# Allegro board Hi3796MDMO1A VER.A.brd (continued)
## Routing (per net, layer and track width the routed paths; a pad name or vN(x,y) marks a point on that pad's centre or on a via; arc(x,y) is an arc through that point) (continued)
VCC_SCI: length 20.9
  TOP w0.508: 108.97,18.8 111.12,20.95 112.39,20.95 114.05,22.61 v1(117.09,22.61)
  BOTTOM w0.508: R243.1 121.08,30.28 117.09,26.29 v1(117.09,22.61)
VDD_AUDIO: length 18.1
  TOP w0.356: U5.9 v1(73.46,90.75)
  TOP w0.381: R174.1 74.22,93.82 v1(73.96,94.08)
  TOP w0.508: R139.2 v1(62.71,92.61)
  BOTTOM w0.508: v1(62.71,92.61) 70.96,92.61 72.83,90.75 v1(73.46,90.75) 73.96,91.25 v1(73.96,94.08)
3136_ADDR0: length 2.4
  TOP w0.127: R3.1 83.64,70.15 84.27,69.52 U2.39
3136_ADDR1: length 2.7
  TOP w0.127: U2.38 84.51,69.92 83.26,71.17 R103.1
3136_DISEQC_IN: length 52.6
  TOP w0.127: v1(94.21,63.2) 94.16,63.25 92.46,63.25 91.95,63.75 91.95,64.26 91.69,64.52 91.69,65.28 91.05,65.92 U2.13
  TOP w0.508: v1(126.11,78.49) 126.24,78.61 Q6.3 126.24,80.67 124.97,81.94 R116.1 123.74,82.58 R51.1
  BOTTOM w0.127: v1(94.21,63.2) 94.69,62.71 104.75,62.71 110.16,68.12 120.4,68.12 126.11,73.84 v1(126.11,78.49)
3136_DISEQC_OUT: length 52.4
  TOP w0.127: U17.9 118.21,69.18 118.42,69.39 119.25,69.39 R123.1 119.77,69.1 120.05,68.82 120.05,58.02 118.7,56.67 110.92,56.67 108.36,54.1 103.28,54.1 102.23,55.14 102.23,55.88 101.42,56.69 101.42,58.5 v1(101.17,58.75) ; v1(91.82,63.12) 91.57,63.37 91.57,64.14 91.14,64.57 90.42,64.57 90.08,64.91 U2.12
  BOTTOM w0.127: v1(91.82,63.12) 91.82,63.02 95.15,59.69 99.03,59.69 99.64,59.08 100.84,59.08 v1(101.17,58.75)
3136_FUNC_SEL: length 3.1
  TOP w0.127: U2.14 91.16,66.32 91.95,65.53 91.95,64.8 R4.1
3136_HV_SEL: length 46
  TOP w0.127: v1(101.22,60.17) 101.75,59.64 101.75,56.72 102.49,55.98 102.49,55.25 103.38,54.36 108.13,54.36 110.74,56.97 118.26,56.97 119.67,58.38 119.67,60.06 118.21,61.52 U17.8 ; v1(92.58,67.97) 92.54,67.92 U2.18
  BOTTOM w0.127: v1(101.22,60.17) 100.97,59.92 99.95,59.92 99.54,60.33 97.45,60.33 96.67,61.1 94.57,61.1 93.81,61.86 93.07,62.61 93.07,67.49 92.63,67.92 92.63,67.92 v1(92.58,67.97)
3136_I2C_SCL: length 19
  TOP w0.127: U2.41 84.54,68.72 84.45,68.81 83.95,68.81 83.5,68.36 83.32,68.36 C221.1 82.83,68.17 82.55,68.45 80.92,68.45 R108.2 80.42,68.05 80,68.47 77.13,68.47 74.3,65.63 74.3,64.34 72.82,62.87 72.72,62.87 72.39,62.53 72.39,62.15 72.14,61.9 71.54,61.9 U10.D26
3136_I2C_SDA: length 17.8
  TOP w0.127: U2.40 84.58,69.12 84.52,69.06 83.82,69.06 83.44,68.68 83.36,68.68 C217.1 82.83,68.99 82.55,68.71 80.95,68.71 R104.2 80.42,69.14 80,68.72 76.9,68.72 73.91,65.74 73.91,64.42 72.21,62.71 72.01,62.51 72.01,62.37 U10.C27
3136_IOUT_N: length 30.5
  TOP w0.114: U2.32 87.28,71.58 87.35,71.65 87.35,76.17 90.3,79.12 95,79.12 98.1,82.22 98.1,89.52 99.93,91.35 101.33,91.35 C307.2
3136_IOUT_P: length 30.5
  TOP w0.114: U2.31 87.68,71.58 87.62,71.65 87.62,72.1 87.73,72.21 87.73,72.53 87.62,72.64 87.62,76.06 90.41,78.85 95.11,78.85 98.36,82.11 98.36,89.41 98.7,89.75 98.97,89.75 99.16,89.94 99.16,90.2 99.35,90.39 99.61,90.39 99.81,90.59 99.81,90.85 100.04,91.08 101.26,91.08 C303.2
3136_LNB_EN: length 45.3
  TOP w0.127: U17.5 116.26,61.06 117.51,59.8 117.51,57.76 116.98,57.23 110.57,57.23 107.95,54.61 103.49,54.61 102.75,55.35 102.75,56.09 102.03,56.8 102.03,60.15 101.45,60.73 100.66,60.73 v1(100.33,60.4) ; v1(91.49,68.81) 91.49,68.94 91.31,69.12 U2.21
  BOTTOM w0.127: v1(91.49,68.81) 91.77,69.09 92.38,69.09 93.45,68.02 93.45,62.71 94.67,61.49 96.85,61.49 97.66,60.68 100.05,60.68 v1(100.33,60.4)
3136_QOUT_N: length 33.7
  TOP w0.114: C186.2 101.26,93.88 100.4,93.88 96.84,90.32 96.84,82.74 94.49,80.39 89.66,80.39 85.98,76.71 85.98,74.23 86.13,74.08 86.13,73.78 85.98,73.62 85.98,73.32 86.13,73.17 86.13,72.86 85.98,72.71 85.98,71.5 86.08,71.4 U2.35
3136_QOUT_P: length 33.7
  TOP w0.114: U2.36 85.68,71.45 85.71,71.48 85.71,76.82 89.55,80.66 94.38,80.66 96.57,82.85 96.57,90.43 100.29,94.15 101.23,94.15 C306.2
3136_RF_AGC: length 35.6
  TOP w0.127: R60.1 100.19,95.83 95.32,90.96 95.32,83.25 93.85,81.79 88.95,81.79 84.58,77.42 84.58,75.56 83.95,74.93 82.3,74.93 82.02,74.65 C37.1 R127.2
3136_RSTN: length 34.7
  TOP w0.127: U10.C28 74.68,64.24 74.68,65.33 v1(77.22,67.87) ; U2.15 91.14,66.72 91.64,66.22 C38.1 R83.1 92.56,64.85 92.71,64.69 94.61,64.69 94.87,64.44 94.87,62.99 94.41,62.53 86.87,62.53 86.28,63.12 83.57,63.12 v1(83.31,63.37)
  BOTTOM w0.127: v1(77.22,67.87) 78.66,66.42 78.99,66.42 82.04,63.37 v1(83.31,63.37)
3136_TS_CLK: length 3.2
  TOP w0.127: R10.2 83.11,64.82 84.3,66.01 84.3,66.37 84.66,66.72 U2.46
3136_TS_OUT0: length 6.2
  TOP w0.127: U2.48 84.8,65.92 84.58,65.7 84.58,64.64 83.82,63.88 82.93,63.88 82.55,63.5 R13.2
3136_TS_SYNC: length 2.6
  TOP w0.127: R226.2 83.79,67.82 84.35,67.82 84.46,67.92 U2.43
3136_TS_VAL: length 6.5
  TOP w0.127: U2.44 84.06,67.52 83.69,67.16 83.69,66.17 83.36,65.84 R5.2 82.83,66.22 82.7,66.34 80.92,66.34 C176.1
3136_XIN: length 12.9
  TOP w0.203: U2.23 91.6,69.92 92.01,69.51 92.47,69.51 92.81,69.16 R24.1 93.42,69.24 C172.1
  TOP w0.254: C172.1 98.02,69.24 98.68,69.9 X1.2
3136_XOUT: length 12.5
  TOP w0.203: C174.1 93.55,68.15 R24.2 93.07,68.63 92.84,68.63 92.29,69.18 91.86,69.18 91.51,69.52 U2.22
  TOP w0.254: C174.1 95.28,68.15 95.76,68.63 98.3,68.63 98.68,68.25 X1.1
AC2012_SCL_T: length 25.2
  TOP w0.127: U2.27 89.28,71.37 89.75,71.84 89.75,72.46 89.48,72.73 89.47,72.73 R65.2 89.13,73.53 89.26,73.53 89.42,73.7 89.42,75.43 91.72,77.72 95.5,77.72 99.51,81.73 99.51,85.73 101.18,87.4 101.33,87.4 R61.2
AC2012_SDA_T: length 24.5
  TOP w0.127: U2.26 89.68,71.41 90,71.74 90,72.71 90.2,72.9 R66.2 90.02,73.3 89.67,73.65 89.67,75.32 91.82,77.47 95.61,77.47 99.76,81.62 99.76,85.62 101.29,87.15 101.41,87.15 R62.2
ADAC_VOUTL: length 21.8
  TOP w0.203: U10.D23 69.19,61.95 69.19,62.53
  TOP w0.254: 69.19,62.53 69.19,62.81 69.14,62.87 69.14,63.42 70.1,64.39 70.1,66.08 70.48,66.46 70.48,66.47 70.48,79.5 69.52,80.47 R138.1 69.52,81.48 69.46,81.55 C350.2
ADAC_VOUTR: length 20.7
  TOP w0.254: C351.1 68.31,81.6 68.15,81.43 R183.1 68.15,80.06 69.47,78.74 69.47,67.06 68.94,66.52 68.94,63.91 68.76,63.73 68.76,62.35 U10.C23
ADAC_VREF: length 1.9
  TOP w0.254: U10.G18 v2(65.18,59.54)
  BOTTOM w0.381: C250.2 65.96,58.75 v2(65.18,59.54)
AUDIO_L: length 11.3
  TOP w0.254: J34.3 65.53,103.87 65.53,100.2 66.42,99.31 67.99,99.31 68.63,98.67 C339.1 68.61,97.71 68.61,96.69 R119.2
AUDIO_R: length 14
  TOP w0.254: J34.2 66.8,107.7 64.8,105.69 64.8,99.97 66.19,98.58 67.16,98.58 67.54,98.2 C140.1 R74.1
CORE_CTRL: length 4
  TOP w0.127: U10.E27 72.51,61.27 72.83,61.27 73.78,62.22 v1(73.78,62.53)
  BOTTOM w0.127: v1(73.78,62.53) 73.78,63.06 R23.2
CPU_CTRL: length 7.1
  TOP w0.127: U10.E28 72.85,60.74 74.26,62.14 74.26,63.11 75.54,64.39 v1(75.92,64.39)
  BOTTOM w0.127: R21.2 76.58,63.88 76.07,64.39 v1(75.92,64.39)
CVBS: length 37.3
  TOP w0.254: U10.A25 70.61,64.17 70.61,65.02 71.75,66.17 71.75,80.9 72.14,81.28 72.14,85.09 74.47,87.43 76.22,87.43 78.26,89.46 R9.1 C79.1 78.26,95.92 L6.1 78.26,95.95 C80.1
CVBS_OUT: length 15.2
  TOP w0.305: L6.2 77.46,96.94 C80.2 C17.1 76.31,97.97 76,97.66 D9.3 74.93,98.93 72.26,101.6 69.55,101.6 69.09,101.14 J34.4
DDR_ADDR0: length 76.2
  TOP w0.127: U10.AF13 61.17,43.54 61.17,39.21 55.62,33.66 54.39,32.43 42.78,32.43 41.74,31.39 34.13,31.39 32.34,33.18 32.34,33.92 30.93,35.32 v2(30.93,40.4) 31.23,40.4 31.56,40.73 31.56,41.23 31.74,41.42 34.39,41.42 34.8,41.82 34.8,42.32 35.39,42.91 U6.N3 ; U3.N3 35.39,59.28 34.75,58.64 34.75,58.27 34.33,57.85 31.62,57.85 31.39,57.63 31.39,57.27 v2(30.93,56.81)
  BOTTOM w0.127: v2(30.93,56.81) 30.68,56.56 30.68,51.7 31.57,50.81 31.57,49.03 30.05,47.5 30.05,43.88 31.56,42.37 31.56,40.98 30.98,40.4 v2(30.93,40.4)
DDR_ADDR1: length 53.3
  TOP w0.127: U6.P7 v2(34.99,39.43) ; U3.P7 v2(34.99,55.84) ; U10.AE12 v2(59.58,44.34)
  BOTTOM w0.127: v2(59.58,44.34) 59.18,43.94 59.18,41.4 52.87,35.1 36.85,35.1 36.01,35.93 36.01,37.22 35.79,37.45 35.79,37.9 35.38,38.3 35.38,38.79 34.99,39.18 v2(34.99,39.43) 34.99,40.69 35.89,41.59 35.89,43.07 34.2,44.76 34.2,45.4 34.62,45.83 34.62,47.57 35,47.96 35,51.8 34.74,52.06 34.74,54.32 35.07,54.64 35.2,54.64 35.38,54.83 35.38,55.44 v2(34.99,55.84)
DDR_ADDR2: length 78.5
  TOP w0.127: U3.P3 34.59,59.33 33.39,58.13 31.42,58.13 v2(30.93,57.65) ; v2(30.93,41.24) 30.93,41.38 31.43,41.87 33.59,41.87 34.59,42.87 U6.P3 ; U10.AD15 v2(62.78,45.14)
  BOTTOM w0.127: v2(62.78,45.14) 63.17,44.74 63.17,43.03 62.76,42.62 62.76,41.08 52.65,30.96 46.35,30.96 44.71,29.32 37.03,29.32 33.83,32.52 33.83,33.59 30.07,37.35 30.07,40.79 30.52,41.24 v2(30.93,41.24) 30.68,41.49 30.68,42.15 29.29,43.54 29.29,47.94 31.19,49.84 31.19,50.68 30.3,51.57 30.3,57.02 v2(30.93,57.65)
DDR_ADDR3: length 65.3
  TOP w0.127: U3.N2 35.76,59.86 35.76,59.04 v2(35.23,58.51) ; v2(35.23,42.1) 35.76,42.63 35.76,43.46 U6.N2 ; v2(43,31.99) 54.67,31.99 62.38,39.69 U10.AH15
  BOTTOM w0.127: v2(35.23,58.51) 35.23,56.64 33.78,55.19 33.78,54.75 34.26,54.27 34.26,51.6 34.24,51.58 34.24,48.37 32.84,46.97 32.84,45.47 32.99,45.32 32.99,44.83 35.23,42.6 v2(35.23,42.1) 34.19,41.06 34.19,35.8 38,31.99 v2(43,31.99)
DDR_ADDR4: length 55.9
  TOP w0.127: U3.P8 v2(34.99,55.04) ; U6.P8 v2(34.99,38.63) ; U10.AD13 v2(60.38,45.14)
  BOTTOM w0.127: v2(34.99,55.04) 34.69,54.74 34.49,54.54 34.49,51.83 34.62,51.7 34.62,48.34 33.24,46.96 33.24,45.15 35.63,42.76 35.63,41.82 34.6,40.78 34.6,39.02 v2(34.99,38.63) 34.99,37.4 34.99,37.39 34.99,35.58 36.43,34.14 52.46,34.14 59.56,41.25 59.56,42.95 59.97,43.36 59.97,44.73 v2(60.38,45.14)
DDR_ADDR5: length 81.2
  TOP w0.127: U10.AE16 v2(63.58,44.34) ; U3.P2 34.97,59.85 34.97,59.27 34.24,58.54 v2(34.24,58.4) ; v2(31.84,33.71) 30.51,35.04 30.51,40.62 30.74,40.84 31.1,40.84 31.33,41.07 31.33,41.38 31.59,41.64 33.93,41.64 v2(34.34,42.05) 34.34,42.24 34.97,42.88 34.97,43.44 U6.P2
  BOTTOM w0.127: v2(34.24,58.4) 34.24,56.1 33.38,55.24 33.38,51.89 33.86,51.42 33.86,48.39 32.18,46.72 32.18,44.79 34.34,42.64 v2(34.34,42.05) ; v2(63.58,44.34) 64.77,43.14 64.77,40.85 51.72,27.79 36.4,27.79 31.92,32.27 31.92,33.63 v2(31.84,33.71)
DDR_ADDR6: length 57.8
  TOP w0.127: U10.AF11 58.8,43.56 58.8,42.98 59.18,42.6 59.18,38.97 53.82,33.61 41.87,33.61 41.16,32.91 36.47,32.91 33.39,35.99 v2(33.39,38.63) U6.R8 ; v2(32.59,55.04) 33.39,55.04 U3.R8
  BOTTOM w0.127: v2(33.39,38.63) 33.39,38.78 33,39.18 33,42.96 31.52,44.44 31.52,47.02 33.1,48.6 33.1,51.21 32.21,52.1 32.21,54.46 32.59,54.84 v2(32.59,55.04)
DDR_ADDR7: length 76.2
  TOP w0.127: U10.AG15 62.81,42.71 62.81,39.49 54.11,30.8 34.11,30.8 30.13,34.78 30.13,41.08 31.15,42.1 33.38,42.1 34.19,42.9 34.19,43.43 U6.R2 33.79,44.09 33.37,44.5 33.37,44.92 32.59,45.7 31.95,45.7 29.11,48.55 29.11,56.46 31.09,58.44 33.34,58.44 34.16,59.27 34.16,59.86 U3.R2
DDR_ADDR8: length 58.7
  TOP w0.127: U10.AG12 59.56,42.72 59.56,38.79 54.01,33.23 42.21,33.23 41.31,32.33 36.44,32.33 32.59,36.18 32.59,38.21 32.59,38.21 v2(32.59,38.63) U6.T8 ; U3.T8 32.11,55.44 v2(31.76,55.09)
  BOTTOM w0.127: v2(31.76,55.09) 31.45,54.77 31.45,51.9 32.34,51.01 32.34,48.8 30.81,47.28 30.81,44.13 32.38,42.56 32.38,40.73 32.08,40.43 32.08,39.13 v2(32.59,38.63)
DDR_ADDR9: length 82.6
  TOP w0.127: U3.R3 33.79,59.32 33.24,58.77 30.85,58.77 28.73,56.64 28.73,48.17 32.66,44.24 33.12,44.24 33.4,43.95 33.4,43.65 33.79,43.26 U6.R3 33.79,42.91 33.21,42.33 30.87,42.33 29.75,41.21 29.75,34.5 v2(31.39,32.86) ; U10.AE17 v2(64.38,44.34)
  BOTTOM w0.127: v2(64.38,44.34) 65.15,43.56 65.15,40.64 51.92,27.41 36.23,27.41 31.39,32.25 v2(31.39,32.86)
DDR_ADDR10: length 48.3
  TOP w0.127: U3.L7 v2(36.59,56.64) ; U10.AE9 v2(57.18,44.34) ; U6.L7 v2(36.59,40.23)
  BOTTOM w0.127: v2(36.59,56.64) 36.98,56.24 36.98,55.67 36.9,55.59 36.9,44.87 37.01,44.77 37.01,40.64 v2(36.59,40.23) 37,39.82 37,39.19 36.93,39.12 36.93,38.47 37.13,38.27 37.13,36.69 37.67,36.15 38.28,36.15 38.37,36.24 52.26,36.24 57.53,41.51 57.53,42.98 57.66,43.1 57.66,43.86 v2(57.18,44.34)
DDR_ADDR11: length 56
  TOP w0.127: U10.AG10 58.38,42.89 58.8,42.47 58.8,39.13 53.66,33.99 41.56,33.99 40.86,33.29 36.69,33.29 34.19,35.8 34.19,39.43 U6.R7 v2(33.39,39.43) ; U3.R7 v2(33.39,55.84)
  BOTTOM w0.127: v2(33.39,39.43) 33.39,43.08 31.85,44.61 31.85,46.87 33.48,48.5 33.48,51.31 32.59,52.2 32.59,54.34 33.09,54.84 33.09,55.54 v2(33.39,55.84)
DDR_ADDR12: length 50.8
  TOP w0.127: U10.AE11 v2(58.78,44.34) ; U3.N7 v2(35.79,55.84) ; U6.N7 v2(35.79,39.43)
  BOTTOM w0.127: v2(58.78,44.34) 58.78,41.54 52.72,35.48 37.1,35.48 36.6,35.98 36.6,37.84 36.18,38.25 36.18,39.03 v2(35.79,39.43) 35.79,40.53 36.42,41.16 36.42,43.85 35.79,44.49 35.79,45.4 36.22,45.84 36.22,53.43 35.79,53.86 35.79,54.24 36.22,54.67 36.22,55.18 35.79,55.61 v2(35.79,55.84)
DDR_ADDR13: length 81.2
  TOP w0.127: U3.T3 32.69,59.44 32.64,59.49 30.46,59.49 27.97,57 27.97,47.66 32.21,43.42 32.6,43.42 U6.T3 32.91,42.94 31.59,42.94 31.25,43.29 29.47,43.29 28.98,42.8 28.98,33.97 33.41,29.54 53.49,29.54 63.37,39.42 63.37,40.89 64.64,42.16 64.64,43.27 U10.AF17
DDR_ADDR14: length 59.5
  TOP w0.127: U3.T7 v2(32.59,55.84) ; U10.AF12 v2(60.38,43.54) ; U6.T7 v2(32.59,39.43)
  BOTTOM w0.127: v2(32.59,55.84) 32.15,55.4 32.15,54.92 31.83,54.6 31.83,52 32.72,51.11 32.72,48.7 31.19,47.17 31.19,44.26 32.61,42.84 32.61,39.87 32.59,39.85 v2(32.59,39.43) 32.59,39.18 32.98,38.79 32.98,38.35 32.34,37.7 32.34,36.81 32.77,36.37 33.03,36.37 37.92,31.48 43.37,31.48 45.32,33.42 52.28,33.42 59.94,41.09 59.94,42.88 60.38,43.31 v2(60.38,43.54)
DDR_ADDR15: length 50.6
  TOP w0.127: U10.AD11 v2(58.78,45.14) ; U6.M7 v2(36.59,39.43) ; U3.M7 v2(35.79,56.64)
  BOTTOM w0.127: v2(35.79,56.64) 35.79,56.45 36.19,56.05 36.19,55.64 36.58,55.25 36.58,44.61 36.73,44.46 36.73,41.01 36.12,40.4 36.12,39.9 v2(36.59,39.43) 36.59,38.33 36.85,38.06 36.85,36.36 37.35,35.86 52.47,35.86 57.91,41.3 57.91,42.65 58.37,43.1 58.37,44.73 v2(58.78,45.14)
DDR_BA0: length 80.5
  TOP w0.127: U10.AH16 v2(63.58,41.94) ; v2(32.88,33.34) 32.88,34.01 31.32,35.57 31.32,39.77 32.43,40.88 35.14,40.88 36.58,42.32 36.58,43.29 36.19,43.68 U6.M2 36.07,43.94 35.85,43.94 35.58,44.21 35.28,44.21 35,44.49 35,45.01 35,45.01 35,45.43 34.73,45.7 33.22,45.7 32.72,46.21 32.08,46.21 29.49,48.8 29.49,54.35 32.36,57.22 34.95,57.22 36.6,58.87 36.6,59.82 U3.M2
  BOTTOM w0.127: v2(63.58,41.94) 63.58,40.77 52.93,30.12 46.71,30.12 45.14,28.56 36.71,28.56 32.88,32.39 v2(32.88,33.34)
DDR_BA1: length 53.2
  TOP w0.127: U6.N8 v2(35.79,38.63) 35.79,37.43 35.96,37.25 35.96,35.33 35.81,35.18 35.81,34.76 36.82,33.75 40.61,33.75 41.23,34.38 53.5,34.38 57.98,38.85 57.98,43.54 U10.AF10 ; U3.N8 v2(35.79,55.04)
  BOTTOM w0.127: v2(35.79,55.04) 35.79,54.78 35.42,54.4 35.23,54.4 35,54.17 35,52.27 35.38,51.88 35.38,47.78 35,47.39 35,44.67 36.14,43.52 36.14,41.36 35.4,40.62 35.4,39.19 35.79,38.8 v2(35.79,38.63)
DDR_BA2: length 73
  TOP w0.127: U3.M3 36.19,58.89 34.83,57.52 32.06,57.52 v2(31.95,57.42) ; U6.M3 36.19,42.44 34.91,41.16 32.1,41.16 v2(31.95,41.01) ; U10.AE13 v2(60.38,44.34)
  BOTTOM w0.127: v2(60.38,44.34) 60.38,44.09 60.83,43.64 60.83,42.6 60.33,42.09 60.33,40.93 52.34,32.94 45.47,32.94 43.62,31.1 37.54,31.1 31.57,37.07 31.57,40.63 v2(31.95,41.01) 31.95,42.48 30.43,44 30.43,47.38 31.95,48.9 31.95,50.91 31.07,51.8 31.07,55.73 31.95,56.62 v2(31.95,57.42)
DDR_CASN: length 83.9
  TOP w0.127: U3.K3 v2(38.19,59.04) ; U10.AE15 v2(62.78,44.34) ; U6.K3 37.79,43.29 37.39,43.69 37.39,45.02 v2(37.69,45.32) 37.69,45.57 34.09,49.16 v2(31.11,49.16)
  BOTTOM w0.127: v2(38.19,59.04) 37.89,58.74 37.89,57.57 37.93,57.54 37.93,57.53 38.16,57.3 38.16,57.3 38.48,56.99 38.48,53.76 38.2,53.48 38.2,47.28 38.38,47.1 38.38,46.02 v2(37.69,45.32) ; v2(62.78,44.34) 62.37,43.93 62.37,41.22 52.62,31.47 46.1,31.47 44.33,29.7 37.19,29.7 34.23,32.65 34.23,33.85 30.52,37.56 30.52,40.65 30.71,40.84 31.1,40.84 31.33,41.07 31.33,41.4 31.07,41.66 31.07,42.27 29.67,43.67 29.67,47.72 v2(31.11,49.16)
DDR_CKE: length 45
  TOP w0.127: U3.K9 v2(37.39,54.24) ; v2(38.28,37.1) 37.79,37.59 U6.K9 ; U10.AD10 v2(57.98,45.14)
  BOTTOM w0.127: v2(37.39,54.24) 37.18,54.03 37.18,45.15 37.49,44.84 37.49,41.97 37.88,41.58 37.88,39.72 37.88,39.72 37.88,39.13 38.28,38.74 v2(38.28,37.1) 52.52,37.1 56.77,41.35 R130.2 56.77,42.97 56.77,42.98 56.77,44.53 56.99,44.74 57.58,44.74 v2(57.98,45.14)
DDR_CLK1N: length 45.4
  TOP w0.114: R37.1 55.36,37.94 52.21,34.79 41.36,34.79 39.38,36.77 39.25,36.77 38.47,37.55 38.47,37.83 38.23,38.07 38.23,39.17 37.79,39.6 U6.K7 ; U3.K7 38.06,56.5 38.06,56.82 38.59,57.35 38.59,57.48 v2(38.37,57.7)
  TOP w0.127: U6.K7 37.79,40.33 38.31,40.86 v2(38.61,40.86)
  BOTTOM w0.114: R11.2 38.72,58.08 38.72,57.95 38.47,57.7 v2(38.37,57.7) 38.73,57.34 38.73,40.99 v2(38.61,40.86) 38.82,40.65 38.82,39.83 R15.2
DDR_CLK1P: length 44.8
  TOP w0.114: v2(39.08,57.7) 38.86,57.48 38.86,57.24 38.32,56.71 38.32,56.5 U3.J7 ; U6.J7 38.99,39.43 38.99,38.14 38.73,37.89 38.73,37.66 39.36,37.03 39.49,37.03 40.08,36.44 40.25,36.44 40.3,36.44 40.51,36.22 40.51,36.06 40.51,36.01 40.73,35.79 40.89,35.79 40.97,35.79 41.16,35.6 41.16,35.41 41.16,35.36 41.47,35.05 52.1,35.05 55.24,38.19 R36.1
  TOP w0.127: v2(39.32,40.86) 39.18,40.86 38.81,40.49 38.81,40.05 U6.J7
  BOTTOM w0.114: R15.1 39.08,39.81 39.08,40.63 v2(39.32,40.86) 39.14,40.86 39,41 39,57.62 v2(39.08,57.7) 38.99,57.79 38.99,58.06 R11.1
DDR_CSN: length 73.5
  TOP w0.127: U10.AH13 60.78,39.36 54.26,32.85 42.52,32.85 41.55,31.88 36.31,31.88 32.08,36.1 32.08,39.64 32.82,40.38 35.65,40.38 37.41,42.14 37.41,43.26 36.99,43.68 U6.L2 36.99,44.01 36.59,44.41 36.59,45.49 35.62,46.46 33.73,46.46 32.97,47.23 32.34,47.23 30.25,49.31 30.25,54.18 32.7,56.63 35.2,56.63 37.39,58.81 37.39,59.84 U3.L2
DDR_DM0: length 16.8
  TOP w0.127: v2(42.19,55.84) U3.E7 ; U10.R4 v2(53.18,52.34)
  BOTTOM w0.127: v2(53.18,52.34) 52.58,51.74 50.04,51.74 48.26,53.52 48.26,55.55 46.16,57.65 44.01,57.65 v2(42.19,55.84)
DDR_DM1: length 16.7
  TOP w0.127: U10.T5 54.38,51.94 v2(53.98,52.34) ; U3.D3 v2(42.99,59.84)
  BOTTOM w0.127: v2(53.98,52.34) 53.57,52.74 51.68,52.74 51.18,52.25 50.27,52.25 48.64,53.88 48.64,55.76 45.17,59.23 43.6,59.23 v2(42.99,59.84)
DDR_DM2: length 11.1
  TOP w0.127: U6.E7 v2(42.19,40.23) ; U10.AF1 v2(50.78,43.54)
  BOTTOM w0.127: v2(50.78,43.54) 47.47,40.23 v2(42.19,40.23)
DDR_DM3: length 11.3
  TOP w0.127: U10.AE2 v2(51.58,44.34) ; U6.D3 v2(42.99,42.63)
  BOTTOM w0.127: v2(42.99,42.63) 43.6,42.02 47.68,42.02 50.44,44.78 51.13,44.78 v2(51.58,44.34)
DDR_DQ0: length 18.9
  TOP w0.127: U10.N4 v2(53.18,54.74) ; U3.E3 v2(41.39,59.84)
  BOTTOM w0.127: v2(41.39,59.84) 41.39,60.57 41.91,61.09 41.91,61.85 42.22,62.16 44.72,62.16 47.1,59.77 47.1,59.45 49.91,56.64 49.91,55.75 51.33,54.33 52.77,54.33 v2(53.18,54.74)
DDR_DQ1: length 13.5
  TOP w0.127: U3.F7 41.38,55.84 41.38,54.43 42.24,53.58 45.48,53.58 48.59,50.47 51.04,50.47 U10.V1
DDR_DQ2: length 16.5
  TOP w0.127: U3.F2 41.39,60.64 41.39,61.93 41.93,62.47 44.83,62.47 46.23,61.07 46.23,59.69 47.5,58.42 49.16,56.76 49.16,55.91 50.73,54.34 U10.N1
DDR_DQ3: length 15.8
  TOP w0.127: U10.W3 52.35,49.96 50.98,49.96 50.88,50.06 50.32,50.06 50.22,49.96 47.8,49.96 44.7,53.07 41.46,53.07 40.6,53.93 40.6,55.04 U3.F8
DDR_DQ4: length 21.2
  TOP w0.127: v2(40.59,59.84) 39.79,59.84 U3.H3 ; U10.N5 v2(53.98,54.74)
  BOTTOM w0.127: v2(53.98,54.74) 53.57,55.14 51.28,55.14 50.35,56.08 50.35,57.45 47.75,60.05 47.47,60.05 44.95,62.57 42.04,62.57 41.61,62.13 41.61,61.34 40.59,60.33 v2(40.59,59.84)
DDR_DQ5: length 17.8
  TOP w0.127: U3.H8 39,55.04 39,53.93 41.34,51.59 44.17,51.59 46.89,48.87 51.49,48.87 51.71,49.1 52.41,49.1 U10.Y3
DDR_DQ6: length 18.5
  TOP w0.127: U3.G2 40.59,60.63 40.59,61.95 41.48,62.85 44.99,62.85 46.74,61.1 46.74,59.72 49.54,56.92 49.54,56.07 50.82,54.79 51.52,54.79 U10.N2
DDR_DQ7: length 16.8
  TOP w0.127: U10.W2 51.67,49.54 51.28,49.15 50.29,49.15 50.06,49.38 47.63,49.38 44.45,52.56 41.17,52.56 39.8,53.93 39.8,55.83 U3.H7
DDR_DQ8: length 15.8
  TOP w0.127: v2(42.99,55.84) U3.D7 ; v2(53.18,51.54) 53.58,51.14 U10.U4
  BOTTOM w0.127: v2(53.18,51.54) 52.79,51.16 49.99,51.16 47.88,53.27 47.88,55.3 45.9,57.27 44.42,57.27 42.99,55.84 v2(42.99,55.84)
DDR_DQ9: length 11.9
  TOP w0.127: U10.R2 51.71,52.74 51.05,53.39 50.47,53.39 48.26,55.6 48.26,56.58 45.83,59.01 44.02,59.01 43.6,59.44 U3.C3
DDR_DQ10: length 15.8
  TOP w0.127: v2(43.79,55.84) U3.C8 ; U10.U5 v2(53.98,50.74)
  BOTTOM w0.127: v2(53.98,50.74) 53.58,50.34 51.46,50.34 51.21,50.6 49.91,50.6 47.49,53.01 47.49,55.05 45.65,56.89 44.84,56.89 v2(43.79,55.84)
DDR_DQ11: length 16.9
  TOP w0.127: U3.C2 43,60.63 43,61.82 43.26,62.08 44.65,62.08 45.85,60.89 45.85,59.53 48.71,56.67 48.71,55.69 50.63,53.77 51.05,53.77 51.69,53.14 52.38,53.14 U10.P3
DDR_DQ12: length 12.7
  TOP w0.127: U3.A7 45.38,56.24 v2(45.54,56.4) ; U10.V4 v2(53.18,49.94)
  BOTTOM w0.127: v2(53.18,49.94) 51.13,49.94 50.92,50.14 49.81,50.14 47.11,52.84 47.11,54.87 45.59,56.4 v2(45.54,56.4)
DDR_DQ13: length 12.8
  TOP w0.127: U3.A2 v2(45.39,60.64) ; U10.P4 v2(53.18,53.94)
  BOTTOM w0.127: v2(45.39,60.64) 46.2,59.82 46.2,59.64 49.51,56.33 49.51,55.27 51.23,53.54 52.78,53.54 v2(53.18,53.94)
DDR_DQ14: length 13.7
  TOP w0.127: U10.W4 v2(53.18,49.14) ; v2(44.59,55.84) U3.B8
  BOTTOM w0.127: v2(44.59,55.84) 45.51,55.84 46.73,54.61 46.73,52.54 50.13,49.14 v2(53.18,49.14)
DDR_DQ15: length 13.5
  TOP w0.127: U3.A3 v2(45.39,59.84) ; U10.P5 v2(53.98,53.94)
  BOTTOM w0.127: v2(53.98,53.94) 53.18,53.14 51,53.14 49.05,55.09 49.05,56.02 45.78,59.29 45.78,59.45 v2(45.39,59.84)
DDR_DQ16: length 16.5
  TOP w0.127: U10.AA5 v2(53.98,47.54) ; U6.E3 v2(41.39,43.43)
  BOTTOM w0.127: v2(53.98,47.54) 53.46,48.06 52.07,48.06 51.18,47.17 49.53,47.17 48.1,45.74 42.53,45.74 42.11,45.32 42.11,44.81 41.39,44.09 v2(41.39,43.43)
DDR_DQ17: length 20.8
  TOP w0.127: U10.AF6 55.18,43.67 54.79,43.28 54.79,42.93 54.48,42.62 54.48,41.07 50.22,36.81 42.63,36.81 42.18,37.25 42.18,38.5 42.03,38.65 41.55,38.65 41.38,38.82 41.38,39.43 U6.F7
DDR_DQ18: length 13.3
  TOP w0.127: U10.AA2 51.81,47.94 51.46,48.29 50.34,48.29 49.79,47.73 44.45,47.73 42.11,45.39 41.93,45.39 41.39,44.85 41.39,44.23 U6.F2
DDR_DQ19: length 20
  TOP w0.127: U10.AG6 55.18,42.91 54.74,42.47 54.74,40.69 50.48,36.43 42.22,36.43 41.38,37.27 41.38,38.38 40.99,38.78 U6.F8
DDR_DQ20: length 17.8
  TOP w0.127: U10.Y5 v2(53.98,48.34) ; U6.H3 v2(39.79,43.43)
  BOTTOM w0.127: v2(39.79,43.43) 40,43.43 41.73,45.16 41.73,45.57 42.43,46.27 47.49,46.27 49.78,48.56 53.75,48.56 v2(53.98,48.34)
DDR_DQ21: length 22.5
  TOP w0.127: U10.AH7 55.88,42.24 55.88,41.27 55.5,40.89 55.5,40.08 51.09,35.67 41.81,35.67 40.55,36.93 40.32,36.93 39.76,37.5 39.76,38.38 39.39,38.75 U6.H8
DDR_DQ22: length 15.5
  TOP w0.127: U10.AA3 52.47,47.94 52.07,48.34 51.82,48.34 51.59,48.56 50.06,48.56 49.74,48.24 43.69,48.24 41.28,45.83 40.97,45.83 40.59,45.44 40.59,44.23 U6.G2
DDR_DQ23: length 24
  TOP w0.127: U10.AF7 55.58,43.54 55.58,41.48 55.12,41.02 55.12,40.31 50.86,36.05 41.99,36.05 40.56,37.47 40.56,38.47 40.38,38.65 39.98,38.65 39.79,38.83 39.79,39.42 U6.H7
DDR_DQ24: length 18.2
  TOP w0.127: U6.D7 43,39.42 43,38.78 43.15,38.62 43.66,38.62 43.81,38.47 43.81,37.58 44.2,37.19 49.99,37.19 54.23,41.43 54.23,42.6 53.98,42.85 53.98,43.54 U10.AF5
DDR_DQ25: length 10.6
  TOP w0.127: U10.AB1 50.44,47.14 50.08,46.78 45.2,46.78 43.8,45.37 43.8,43.43 U6.C3
DDR_DQ26: length 13.6
  TOP w0.127: U6.C8 43.7,39.03 44.1,38.63 50.88,38.63 53.92,41.68 53.92,42.52 53.58,42.87 U10.AG4
DDR_DQ27: length 12.5
  TOP w0.127: U10.AB3 52.39,47.52 50.85,47.52 50.78,47.45 50.27,47.45 50.06,47.24 44.9,47.24 42.98,45.33 42.98,44.23 U6.C2
DDR_DQ28: length 8.8
  TOP w0.127: U6.A7 45.14,39.98 50.42,39.98 U10.AH3
DDR_DQ29: length 10.3
  TOP w0.127: U6.A2 45.5,43.83 v2(45.9,44.23) ; U10.AA4 v2(53.18,47.54)
  BOTTOM w0.127: v2(53.18,47.54) 52.74,47.54 51.37,46.16 49.66,46.16 47.73,44.23 v2(45.9,44.23)
DDR_DQ30: length 11.4
  TOP w0.127: U6.B8 44.6,39.43 50.43,39.43 53.14,42.14 53.14,42.78 U10.AG3
DDR_DQ31: length 11.1
  TOP w0.127: U6.A3 v2(45.39,43.43) ; U10.AB4 v2(53.98,46.74)
  BOTTOM w0.127: v2(45.39,43.43) 47.95,43.43 50.04,45.52 51.82,45.52 53.04,46.74 v2(53.98,46.74)
DDR_DQS0N: length 15.7
  TOP w0.114: U10.T1 51.09,52.02 50.77,52.02 50.62,51.87 50.44,51.87 50.29,52.02 50.14,52.02 49.82,52.34 49.57,52.34 49.37,52.53 49.37,52.69 49.37,52.79 49.18,52.98 48.92,52.98 48.73,53.18 48.73,53.34 48.73,53.44 47.36,54.8 47.36,56.46 45.79,58.02 41.23,58.02 40.46,58.79 40.46,59.17 U3.G3
DDR_DQS0P: length 15.8
  TOP w0.114: U10.T2 51.7,51.94 51.35,52.29 50.25,52.29 47.62,54.91 47.62,56.57 45.9,58.29 41.34,58.29 40.72,58.9 40.72,59.17 U3.F3
DDR_DQS1N: length 13.7
  TOP w0.114: U10.U3 52.41,50.77 51.64,50.77 51.49,50.93 49.17,50.93 46.34,53.76 46.34,56.3 45.75,56.9 44.07,56.9 43.92,56.75 43.92,56.5 U3.B7
DDR_DQS1P: length 13.7
  TOP w0.114: U3.C7 43.66,56.5 43.66,56.86 43.96,57.16 45.86,57.16 46.61,56.41 46.61,53.87 47.77,52.7 48.01,52.7 48.22,52.49 48.22,52.26 48.42,52.05 48.66,52.05 48.86,51.85 48.86,51.61 49.28,51.19 49.64,51.19 49.78,51.33 50.09,51.33 50.23,51.19 50.55,51.19 50.69,51.33 51.01,51.33 51.15,51.19 51.6,51.19 51.69,51.1 51.94,51.1 U10.U2
DDR_DQS2N: length 15
  TOP w0.114: U6.G3 40.58,42.64 40.58,42.05 40.91,41.72 45.13,41.72 49.38,45.97 49.63,45.97 49.82,45.78 49.97,45.78 50.16,45.97 50.31,45.97 50.5,45.78 50.66,45.78 50.85,45.97 51.62,45.97 51.74,46.09 51.74,46.23 51.84,46.34 U10.AC2
DDR_DQS2P: length 15
  TOP w0.114: U10.AC3 52.52,46.34 52.15,46.71 51.84,46.71 51.37,46.24 49.27,46.24 45.02,41.99 41.02,41.99 40.84,42.16 40.84,42.88 U6.F3
DDR_DQS3N: length 10.9
  TOP w0.114: U6.B7 43.92,40.09 43.92,40.39 44.15,40.62 46.11,40.62 50.62,45.14 51.28,45.14 51.68,45.54 U10.AD2
DDR_DQS3P: length 10.9
  TOP w0.114: U6.C7 43.66,40.09 43.66,40.5 44.04,40.89 46,40.89 48.59,43.48 48.59,43.77 48.76,43.94 49.05,43.94 49.18,44.07 49.18,44.19 49.18,44.35 49.36,44.53 49.48,44.53 49.64,44.53 49.82,44.71 49.82,44.83 49.82,45 50,45.18 50.13,45.18 50.29,45.18 50.51,45.4 51.04,45.4 U10.AD1
DDR_ODT: length 85.7
  TOP w0.127: U3.K1 v2(38.19,60.64) ; U10.AG16 v2(63.58,42.74) ; v2(30.68,49.92) 33.95,49.92 37.48,46.39 37.49,46.39 v2(37.76,46.11) 38.1,45.78 38.1,44.94 U6.K1
  BOTTOM w0.127: v2(37.76,46.11) 37.49,46.39 37.49,53.69 37.97,54.18 37.97,56.76 37.44,57.29 37.44,59.88 v2(38.19,60.64) ; v2(63.58,42.74) 63.14,42.31 63.14,40.92 52.74,30.52 46.54,30.52 44.96,28.94 36.87,28.94 33.39,32.41 33.39,33.47 29.69,37.17 29.69,41.02 30.3,41.64 30.3,42.02 28.91,43.42 28.91,48.15 v2(30.68,49.92)
DDR_PLL: length 11.5
  TOP w0.254: v2(61.18,48.34) U10.Y14 60.86,49.45 58.55,49.45 58.17,49.83 58.17,51.35 U10.T9 v2(57.18,51.54)
  BOTTOM w0.381: v2(61.18,48.34) 61.57,47.94 C264.1 ; v2(57.18,51.54) 57.73,52.1 C270.1 57.89,52.65 57.78,52.76 57.78,53.24 C11.1 57.81,54.17 LB7.1
DDR_RASN: length 89.3
  TOP w0.127: v2(64.25,42.36) 64.25,42.86 U10.AG17 ; U6.J3 38.93,43.37 38.93,44.95 38.69,45.19 38.69,46.08 v2(37.92,46.84) 34.18,50.59 v2(30.68,50.59) ; U3.J3 v2(38.19,59.84)
  BOTTOM w0.127: v2(37.92,46.84) 37.87,46.9 37.87,53.61 38.22,53.96 38.22,56.88 37.67,57.44 37.67,59.31 v2(38.19,59.84) ; v2(30.68,50.59) 28.53,48.43 28.53,37.7 32.34,33.89 32.34,32.39 36.55,28.18 45.44,28.18 46.93,29.66 53.01,29.66 64.25,40.9 v2(64.25,42.36)
DDR_RESETN: length 77.7
  TOP w0.127: U10.AG14 v2(61.98,42.74) ; U3.T2 v2(33.39,59.84) 33.39,59.27 33.17,59.05 30.56,59.05 28.35,56.84 28.35,47.91 32.43,43.83 U6.T2 32.99,43.65 33.38,43.27 33.38,42.88 33.12,42.62 31.42,42.62 31.24,42.8 R26.1 29.36,41.4 29.36,34.17 33.33,30.21 v1(37.8,30.21)
  BOTTOM w0.127: C314.1 61.83,42.88 v2(61.98,42.74) 61.98,41.41 52.6,32.03 46,32.03 44.18,30.21 v1(37.8,30.21) ; C313.1 32.67,59.84 v2(33.39,59.84)
DDR_VREF_CA_A: length 7.2
  TOP w0.203: U3.M8 36.6,55.03 36.6,54.37 36.8,54.17
  TOP w0.381: R158.2 C207.2 C289.1 R159.1 36.58,52.37 36.8,52.6 36.8,54.17
DDR_VREF_CA_B: length 6.9
  TOP w0.203: U6.M8 36.57,38.64 36.57,37.9 36.84,37.63
  TOP w0.381: 36.84,37.63 36.95,37.52 36.95,35.38 R161.2 C222.2 C310.1 R107.1
DDR_VREF_DQ_A: length 4.4
  TOP w0.254: U3.H1 v2(38.99,61.44)
  BOTTOM w0.381: v2(38.99,61.44) 39.12,61.56 C271.1 R160.1 C208.2 R54.2
DDR_VREF_DQ_B: length 4.9
  TOP w0.305: U6.H1 39.47,44.7 v2(39.47,45.68)
  BOTTOM w0.381: v2(39.47,45.68) 39.6,45.81 39.6,46.4 ; 39.6,47.42 R84.1 ; 39.6,47.42 39.6,46.4 ; 39.6,47.42 39.6,48.44 ; 39.6,46.4 C308.1 ; 39.6,48.44 C223.2 ; 39.6,48.44 39.6,49.45 R78.2
DDR_WEN: length 77.1
  TOP w0.127: v2(61.18,45.14) 61.58,44.74 U10.AE14 ; v2(34.77,32.74) 34.45,33.06 31.7,35.81 31.7,39.69 32.64,40.63 35.39,40.63 36.99,42.23 U6.L3 36.99,43.26 36.6,43.65 36.6,43.97 36.32,44.25 36,44.25 35.78,44.47 35.78,45.43 35.13,46.08 33.48,46.08 32.84,46.72 32.21,46.72 29.87,49.05 29.87,54.28 32.51,56.91 35.05,56.91 36.99,58.85 U3.L3
  BOTTOM w0.127: v2(34.77,32.74) 36.8,30.72 43.84,30.72 45.63,32.5 52.44,32.5 60.71,40.77 60.71,41.96 61.21,42.47 61.21,43.74 60.78,44.17 60.78,44.74 v2(61.18,45.14)
DEMOD0_RESTN: length 76.5
  TOP w0.127: U10.L28 81.4,55.94 84.06,53.28 90.28,53.28 92,51.56 103.38,51.56 105.64,53.82 108.56,53.82 111.05,56.31 119.41,56.31 120.35,55.37 130.81,55.37 133.1,57.66 133.1,66.95 J7.10
DEMOD0_SCL: length 113.4
  TOP w0.127: J7.23 130.38,87.06 132.4,87.06 136.45,83.01 136.45,55.93 132.56,52.04 117.19,52.04 115.45,53.78 112.05,53.78 108.31,50.04 105.99,50.04 104.42,48.46 90.98,48.46 88.34,51.1 82.55,51.1 80.6,53.06 74.79,53.06 v1(74.78,53.04) ; U10.G27 72.39,58.72 73.66,58.72 v1(73.91,58.98)
  BOTTOM w0.127: v1(74.78,53.04) 74.3,53.53 74.3,55.17 74.8,55.68 74.8,57.91 73.91,58.8 v1(73.91,58.98)
DEMOD0_SDA: length 109.1
  TOP w0.127: v1(73.91,59.74) 73.31,59.14 U10.G28 ; J7.24 136.07,81.76 136.07,56.04 132.46,52.43 117.17,52.43 115.56,54.04 111.82,54.04 108.15,50.37 105.74,50.37 104.22,48.84 91.06,48.84 88.54,51.36 82.66,51.36 80.7,53.31 75.69,53.31 75.48,53.52 74.52,53.52 v1(74.04,53.04)
  BOTTOM w0.127: v1(74.04,53.04) 74.04,55.35 74.5,55.81 74.5,57.63 73.41,58.72 73.41,59.23 v1(73.91,59.74)
FE_1V1: length 1.7
  TOP w0.254: U10.K12 v2(59.58,57.14)
  BOTTOM w0.381: C248.1 58.88,56.44 v2(59.58,57.14)
FE_3V3: length 3
  TOP w0.381: U10.E7 v2(55.58,61.14) U10.E6
  BOTTOM w0.381: v2(55.58,61.14) 55.75,60.96 C7.1 56.73,60.4 LB8.1
FE_REXT: length 2
  TOP w0.127: U10.G9 v2(57.18,59.54)
  BOTTOM w0.127: R173.1 56.14,58.5 v2(57.18,59.54)
FUNC_SEL: length 1.3
  TOP w0.127: U10.AF26 v2(71.58,43.54)
  BOTTOM w0.127: v2(71.58,43.54) 71.58,42.9 R42.1
HDMI_TX0N: length 46.1
  TOP w0.114: J26.9 52.2,98.81 51.77,98.38 51.77,97.66 51.02,96.91 51.02,96.47 51.13,96.36 U8.9 U8.2 51.13,94.36 51.04,94.27 51.04,88.4 57.73,81.71 58,81.45 58.96,81.45 64.39,76.02 64.39,61.95 U10.D17
HDMI_TX0P: length 46.1
  TOP w0.114: U10.C17 64.12,62.48 64.12,63.09 63.96,63.26 63.96,63.55 64.12,63.71 64.12,64.01 63.96,64.17 63.96,64.46 64.12,64.63 64.12,64.92 63.96,65.09 63.96,65.38 64.12,65.54 64.12,66.54 63.96,66.7 63.96,66.98 64.12,67.14 64.12,67.71 64.01,67.82 63.89,67.82 63.78,67.94 63.78,68.17 63.89,68.28 64.01,68.28 64.12,68.39 64.12,75.91 58.85,81.18 57.89,81.18 57.54,81.52 50.77,88.29 50.77,94.25 50.63,94.39 U8.1 U8.10 50.63,96.33 50.75,96.45 50.75,97.02 51.5,97.77 51.5,98.48 51.2,98.79 J26.7
HDMI_TX1N: length 46.4
  TOP w0.114: U10.B16 63.53,63.49 63.53,66.27 63.14,66.65 63.14,75.66 61.59,77.21 61.21,77.21 61.04,77.04 60.87,77.04 60.55,77.36 60.55,77.52 60.73,77.7 60.73,78.08 60.25,78.56 59.86,78.56 59.69,78.38 59.53,78.38 59.2,78.71 59.2,78.87 59.38,79.05 59.38,79.43 58.63,80.18 57.87,80.18 49.34,88.71 49.34,94.22 49.46,94.34 U23.5 U23.6 49.46,96.4 49.34,96.52 49.34,96.8 50.23,97.69 50.23,98.37 50.7,98.83 J26.6
HDMI_TX1P: length 46.3
  TOP w0.114: J26.4 49.7,98.68 49.97,98.41 49.97,97.8 49.07,96.91 49.07,96.53 48.96,96.41 U23.7 U23.4 48.96,94.35 49.07,94.23 49.07,88.6 57.76,79.91 58.52,79.91 59.11,79.32 59.11,79.16 58.94,78.98 58.94,78.6 59.42,78.12 59.8,78.12 59.97,78.29 60.14,78.29 60.46,77.97 60.46,77.81 60.28,77.63 60.28,77.25 60.76,76.77 61.15,76.77 61.32,76.95 61.48,76.95 62.88,75.55 62.88,67.53 62.76,67.42 62.7,67.42 62.59,67.3 62.59,67.07 62.7,66.96 62.76,66.96 62.88,66.85 62.88,66.54 63.26,66.16 63.26,65.92 63.14,65.8 63.08,65.8 62.97,65.69 62.97,65.46 63.08,65.35 63.14,65.35 63.26,65.23 63.26,65 63.14,64.89 63.08,64.89 62.97,64.77 62.97,64.55 63.08,64.43 63.14,64.43 63.26,64.32 63.26,64.02 U10.A16
HDMI_TX2N: length 46.2
  TOP w0.114: J26.3 49.2,98.84 48.86,98.5 48.86,98.02 47.84,97 47.84,96.44 47.96,96.33 U23.9 U23.2 47.96,94.36 47.85,94.26 47.85,88.8 61.93,74.73 61.93,66.01 61.95,65.99 62.28,65.66 62.59,65.35 62.59,62.94 62.74,62.79 62.74,61.9 U10.D15
HDMI_TX2P: length 46.1
  TOP w0.114: J26.1 48.2,98.86 48.59,98.46 48.59,98.13 47.57,97.11 47.57,96.45 47.46,96.33 U23.10 U23.1 47.46,94.41 47.59,94.28 47.59,88.69 61.66,74.62 61.66,65.9 61.77,65.79 61.77,65.53 61.9,65.41 62.15,65.41 62.32,65.24 62.32,64.83 62.2,64.72 62.12,64.72 62,64.6 62,64.37 62.12,64.26 62.2,64.26 62.32,64.14 62.32,63.92 62.2,63.8 62.14,63.8 62.03,63.69 62.03,63.46 62.14,63.34 62.2,63.34 62.32,63.23 62.32,62.83 62.47,62.68 62.47,62.43 U10.C15
HDMI_TX_1V1: length 1.1
  TOP w0.254: U10.G16 v2(63.58,59.54) ; U10.H16 v2(63.58,58.74)
HDMI_TX_3V3: length 1.1
  TOP w0.254: U10.E16 v2(63.58,61.14) ; U10.E17 v2(64.38,61.14)
HDMI_TX_CEC: length 44.1
  TOP w0.127: U10.A20 66.38,77.87 57.96,86.28 56.97,86.28 54.4,88.86 R184.2 54.4,92.27 54.79,92.66 U4.3 54.79,93.18 53.76,93.18 53.28,93.66 53.28,95.39 54.2,96.31 J26.13
HDMI_TX_HOTPLUG: length 47.6
  TOP w0.127: U10.D21 67.56,61.92 67.56,62.74 67.31,62.99 67.31,78.44 59.05,86.69 59.05,89.66 58.67,90.04 57.91,90.04 57.32,90.64 C149.1 R8.2 57.32,92.6 57.29,92.63 U4.4 59.14,93.19 60.14,94.18 60.14,95.86 58.9,97.1 58.9,97.48 57.2,99.18 J26.19
HDMI_TX_SCL: length 44.8
  TOP w0.127: J26.15 55.2,97.58 55.67,97.11 R186.1 55.17,96.44 54.79,96.06 U4.1 55.83,95.09 55.92,95 55.92,90.79 56.36,90.34 56.36,87.28 57.02,86.61 58.01,86.61 66.75,77.88 66.75,63.51 U10.B20
HDMI_TX_SDA: length 45.2
  TOP w0.127: J26.16 55.7,98.73 57.45,96.99 R187.1 57.45,95.24 U4.6 56.48,95.09 56.26,94.87 56.26,90.93 56.71,90.49 56.71,87.38 57.19,86.89 58.24,86.89 67.06,78.08 67.06,62.88 67.18,62.76 U10.C21
HDMI_TXCN: length 46
  TOP w0.114: J26.12 53.7,98.81 53.32,98.43 53.32,97.75 52.52,96.95 52.52,96.47 52.63,96.35 U8.6 U8.5 52.63,94.36 52.5,94.23 52.5,88.46 56.19,84.77 57.37,84.77 58.14,84 58.14,83.61 57.75,83.22 57.75,83.06 58.08,82.74 58.24,82.74 58.53,83.03 59.03,83.03 65.34,76.72 65.34,64.75 65.51,64.59 65.51,63.6 65.24,63.33 64.97,63.33 U10.B18
HDMI_TXCP: length 45.9
  TOP w0.114: J26.10 52.7,98.81 53.06,98.45 53.06,97.86 52.25,97.06 52.25,96.5 52.13,96.39 U8.7 U8.4 52.13,94.31 52.24,94.21 52.24,88.35 56.08,84.51 57.26,84.51 57.88,83.89 57.88,83.72 57.49,83.33 57.49,82.95 57.97,82.47 58.35,82.47 58.64,82.77 58.92,82.77 65.07,76.61 65.07,65.25 64.92,65.1 64.92,64.8 65.09,64.62 65.24,64.48 65.24,63.71 65.13,63.6 64.83,63.6 64.78,63.66 U10.A18
IR_IN: length 49.8
  TOP w0.127: v1(84.84,19.86) 84.18,19.2 83.85,19.2 80.77,16.13 73.91,16.13 73.15,15.37 73.15,14.22 72.93,14 R140.1 71.98,13.49 D3.1 ; v1(85.6,21.74) 85.11,21.74 69.72,37.13 69.72,42.6 69.58,42.74 U10.AG24
  BOTTOM w0.127: v1(84.84,19.86) 84.84,20.98 v1(85.6,21.74)
JTAG_SEL: length 8
  TOP w0.127: U10.F26 72.84,59.94 73.57,60.67 73.57,61 75.44,62.87 75.95,62.87 76.83,63.75 R96.1
LED0_BASE: length 48.8
  TOP w0.127: R67.2 R219.2 25.53,87.28 25.4,87.15 25.4,85.47 28.57,82.3 34.29,82.3 34.8,81.79 41.66,81.79 42.16,82.3 44.45,82.3 50.8,75.95 50.8,70.61 49.4,69.22 49.4,64.26 50.93,62.74 51.57,62.74 U10.C2
LED0_LINK_ACT: length 35.5
  TOP w0.127: U10.B1 50.55,63.77 50.55,64.33 51.31,65.09 51.31,65.53 50.6,66.24 50.6,68.02 v1(50.29,68.33) ; v1(53.59,68.33) 53.98,68.71 53.98,76.83 43.5,87.31 v1(42.89,87.31) 42.43,86.85 R218.2 R185.2
  BOTTOM w0.127: v1(50.29,68.33) v1(53.59,68.33)
LED_CLK: length 35.6
  TOP w0.127: U10.AH23 68.96,42.15 68.96,36.67 85.19,20.45 86.41,20.45 87.63,19.23 R22.1 R57.1 R147.2
LED_DATA: length 44.6
  TOP w0.127: R31.1 R148.1 90.83,15.39 91.57,16.13 R122.2 92.18,16.87 92.46,17.14 92.46,20.62 92.2,20.88 85.16,20.88 69.22,36.82 69.22,42.4 68.78,42.84 U10.AG23
LED_KEY0: length 53.4
  TOP w0.127: U10.AF23 69.16,43.55 69.16,42.77 69.47,42.47 69.47,36.96 85.2,21.23 96.37,21.23 98.17,19.43 C21.1 R41.2 96.86,12.69 S9.1
LNB_PWR: length 61.5
  TOP w0.381: D27.1 121.79,92.74 121.63,92.9 C104.1 C78.1 120.9,94.42 120.9,95.31 119.55,95.31 119.55,96.07 120.9,96.07 120.9,96.84 C58.1 118.64,101.97 117.88,101.97 117.88,97.98 117.09,97.98 117.09,101.97 116.33,101.97 116.33,97.98 114.5,97.98 114.5,99.59 C64.1
  TOP w0.508: J16.2 114.5,99.59 ; D27.1 122.68,92.33 122.94,92.07 C170.1 122.94,89.41 122.53,89 C155.2 122.53,84.05 122.05,83.57 122.05,81.15 122.43,80.77 122.43,78.23 122.94,77.72 124.84,77.72 D17.2
LNB_PWR_B: length 52.1
  TOP w0.381: R166.2 101.9,105.6 103.79,105.6 103.79,100.39 104.55,100.39 104.55,107.94 106.53,107.94 106.53,105.64 C287.1 106.53,102.87 109.35,102.87 C288.1 C166.1 120.42,106.21 122.73,103.91 122.73,95.52 D27.2
LOOPTHROUGH: length 8
  TOP w0.381: R166.1 99.52,104.05 J16.1
  TOP w0.508: C283.1 J16.1
MUTE_CTRL: length 34.1
  TOP w0.127: U10.A22 67.93,63.99 67.93,67.04 68.33,67.44 68.33,77.98 61.59,84.71 61.59,92.33 62.99,93.73 R90.1
NF_ALE_EMMC_PWREN: length 46.6
  TOP w0.127: U19.17 110.22,35.7 109.6,36.32 109.6,37.68 103.55,43.74 90.17,43.74 86.11,47.8 80.72,47.8 79.96,48.56 77.22,48.56 76.07,49.71 71.35,49.71 U10.W26
NF_CLE: length 59.3
  TOP w0.127: U19.16 v1(109.98,35.2) ; v1(115.57,37.21) 115.57,39.92 114.72,40.77 112.16,40.77 111.22,41.71 107.47,41.71 104.29,44.88 90.17,44.88 86.49,48.56 81.28,48.56 79.66,50.19 77.09,50.19 76.69,50.59 73.41,50.59 73.3,50.7 71.54,50.7 U10.V26
  BOTTOM w0.127: v1(115.57,37.21) 114.81,36.45 111.23,36.45 v1(109.98,35.2)
NF_CSN0_EMMC_CMD: length 68.5
  TOP w0.127: v1(103.09,32.5) 103.38,32.2 U22.W5 ; v1(109.83,31.7) U19.9 111.97,31.7 112.31,32.04 112.79,32.04 113.16,31.67 R212.2 113.64,32.17 113.91,32.44 114.81,32.44 115.03,32.65 115.03,39.88 114.6,40.31 112.01,40.31 111,41.33 107.21,41.33 104.04,44.5 90.13,44.5 86.32,48.31 81.15,48.31 79.52,49.93 76.98,49.93 76.58,50.34 U10.V28
  BOTTOM w0.127: v1(109.83,31.7) 108.05,33.48 104.06,33.48 v1(103.09,32.5)
NF_DQ0_EMMC_D0: length 38.9
  TOP w0.127: U22.H3 97.29,31.2 v1(97.06,30.98) ; U10.Y28 73.71,47.8 75.56,47.8 76.58,46.79 79.25,46.79 80.01,46.02 84.94,46.02 86.87,44.09 86.87,41.53 88.67,39.73 R189.2 89.17,38.53 90.5,37.2 U19.29 v1(92.71,37.2)
  BOTTOM w0.127: v1(97.06,30.98) 97.92,31.83 97.92,34.67 94.74,37.85 93.35,37.85 v1(92.71,37.2)
NF_DQ1_EMMC_D1: length 44.9
  TOP w0.127: U10.Y26 71.34,48.74 71.7,49.1 72.97,49.1 73.23,48.84 73.23,48.69 73.86,48.06 75.69,48.06 76.71,47.04 79.38,47.04 80.14,46.28 85.07,46.28 87.25,44.1 87.25,41.91 89.53,39.62 92.71,39.62 93.98,38.35 v1(93.98,36.88) 93.8,36.7 U19.30 90.22,36.7 89.41,37.52 R12.2 ; v1(96.28,32.12) 96.58,32.12 97,31.7 U22.H4
  BOTTOM w0.127: v1(93.98,36.88) 94.36,36.88 97.1,34.14 97.1,32.38 96.84,32.12 v1(96.28,32.12)
NF_DQ2_EMMC_D2: length 38.2
  TOP w0.127: v1(92.75,36.2) U19.31 89.46,36.2 89.17,36.5 R29.2 88.67,36.86 88.52,37.01 87,37.01 86.49,37.52 86.49,44.04 84.76,45.77 79.88,45.77 79.12,46.53 76.45,46.53 75.44,47.55 73.53,47.55 72.9,48.18 72.06,48.18 71.81,47.94 U10.AA26 ; v1(96.29,33.13) 96.79,33.13 97.72,32.2 U22.H5
  BOTTOM w0.127: v1(92.75,36.2) 93.14,35.81 94.54,35.81 96.29,34.06 v1(96.29,33.13)
NF_DQ3_EMMC_D3: length 43.5
  TOP w0.089: U22.J2 98.34,30.95 97.88,30.95
  TOP w0.127: 97.88,30.95 96.65,29.72 95.89,29.72 95.5,30.1 95.5,30.86 95.12,31.24 94.49,31.24 93.22,32.51 93.22,35.01 92.52,35.7 U19.32 90.57,35.7 90.35,35.48 R58.2 88.67,35.84 88.52,35.99 86.42,35.99 86.17,36.25 86.17,43.95 84.61,45.52 79.76,45.52 78.99,46.28 76.33,46.28 75.31,47.29 73.41,47.29 72.77,47.93 72.14,47.93 71.78,47.57 70.74,47.57 U10.AA25
NF_DQ4_EMMC_D4: length 39.6
  TOP w0.089: 97.74,31.45 98.34,31.45 U22.J3
  TOP w0.127: v1(94.06,30.94) 93.6,31.39 92.71,31.39 92.52,31.2 U19.41 89.58,31.2 89.36,31.42 R176.2 88.67,31.78 88.52,31.93 86.69,31.93 85.85,32.77 85.85,43.74 84.33,45.26 79.63,45.26 78.87,46.02 76.2,46.02 75.18,47.04 73.24,47.04 73.14,47.14 U10.AB28 ; 97.74,31.45 96.6,31.45 v1(96.12,30.98)
  BOTTOM w0.127: v1(96.12,30.98) 94.09,30.98 v1(94.06,30.94)
NF_DQ5_EMMC_D5: length 42.8
  TOP w0.089: U22.J4 98.34,31.95 97.79,31.95
  TOP w0.127: 97.79,31.95 97.61,31.95 96.94,32.63 95.84,32.63 v1(95.33,32.12) ; v1(93.09,30.91) 92.88,30.7 U19.42 89.58,30.7 89.28,30.4 R177.2 88.67,30.76 88.52,30.91 86.69,30.91 85.47,32.13 85.47,43.66 84.12,45.01 79.38,45.01 78.61,45.77 76.07,45.77 75.06,46.79 71.53,46.79 U10.AB26
  BOTTOM w0.127: v1(95.33,32.12) 95.04,31.83 93.68,31.83 93.09,31.24 v1(93.09,30.91)
NF_DQ6_EMMC_D6: length 48.2
  TOP w0.089: U22.J5 98.5,32.2 98.25,32.45 97.95,32.45
  TOP w0.127: v1(95.33,33.39) 95.59,33.64 96.65,33.64 97.84,32.45 97.95,32.45 ; U10.AC26 71.36,46.52 74.94,46.52 75.95,45.52 78.49,45.52 79.25,44.75 83.85,44.75 85.09,43.51 85.09,31.5 86.69,29.9 88.54,29.9 88.67,29.77 R188.2 89.2,29.39 90.02,30.2 U19.43 92.61,30.2 92.96,29.84 v1(93.85,29.84)
  BOTTOM w0.127: v1(95.33,33.39) 94.38,32.44 93.27,32.44 92.33,31.5 92.33,30.48 92.96,29.84 v1(93.85,29.84)
NF_DQ7_EMMC_D7_BOOT_SEL0: length 51.1
  TOP w0.089: U22.J6 98.34,32.95 97.89,32.95 97.47,33.38
  TOP w0.127: v1(92.99,29.01) 92.29,29.7 U19.44 90.41,29.7 89.08,28.37 R202.2 88.67,28.73 88.52,28.88 86.82,28.88 84.71,30.99 84.71,43.38 83.59,44.5 79.12,44.5 78.38,45.24 77.3,45.24 77.19,45.12 R86.1 76.45,44.63 74.83,46.25 71.6,46.25 71.25,45.9 70.81,45.9 U10.AC25 ; v1(94.06,33.38) 94.61,33.38 95.26,34.02 96.82,34.02 97.47,33.38
  BOTTOM w0.127: v1(92.99,29.01) 91.69,30.3 91.69,31.75 93.32,33.38 v1(94.06,33.38)
NF_RDY0_EMMC_RST: length 79.3
  TOP w0.127: v1(109.77,30.7) U19.7 112.38,30.7 112.68,30.4 112.68,29.99 113.03,29.64 R203.2 C115.1 113.64,31.01 113.79,31.17 115.51,31.17 116.08,31.74 116.08,40.03 114.91,41.2 112.35,41.2 111.41,42.13 107.68,42.13 104.55,45.26 90.17,45.26 86.58,48.85 81.37,48.85 79.78,50.44 77.2,50.44 76.79,50.84 73.51,50.84 73.4,50.95 71.78,50.95 71.6,51.14 U10.U26 ; v2(100.73,31.71) 102.1,31.71 U22.U5
  BOTTOM w0.127: v2(100.73,31.71) 103.3,29.13 103.35,29.13 105.66,29.13 107.23,30.7 v1(109.77,30.7)
NF_REN_EMMC_CLK: length 65.7
  TOP w0.127: U10.W25 70.76,49.15 71.32,49.15 71.58,49.4 74.04,49.4 74.73,48.72 76.07,48.72 76.99,47.8 79.63,47.8 80.39,47.04 85.42,47.04 88.52,43.94 88.52,42.29 90.32,40.49 94.92,40.49 95.12,40.28 105.13,40.28 108.53,36.88 108.53,36.12 108.97,35.69 108.97,31.8 109.56,31.2 U19.8 112.2,31.2 v1(112.54,31.53) ; v1(103.1,33.5) 103.1,33.2 U22.W6
  BOTTOM w0.127: v1(112.54,31.53) 109.78,34.29 103.89,34.29 v1(103.1,33.5)
NF_WEN_EMMC_DET: length 46.6
  TOP w0.127: U19.18 110.24,36.2 109.98,36.46 109.98,37.9 103.76,44.12 90.15,44.12 86.21,48.06 81.03,48.06 79.44,49.64 77.85,49.64 77.7,49.49 R56.2 77.09,49.07 76.2,49.96 72.35,49.96 U10.V27
NF_WP: length 4
  TOP w0.127: U19.19 112.39,36.7 112.6,36.5 R89.1 R215.2
REG2OUT: length 43.7
  TOP w0.203: v1(106.08,92.93) 106.46,93.31 U34.10 ; C225.2 112.1,92.91 U34.25 ; U34.1 110.48,95.32 110.81,95.66 111.06,95.66 111.45,96.04 C414.1 111.42,96.29 110.81,96.29 110.08,95.56 U34.2 ; C130.1 107.94,96.52 108.12,96.52 108.4,96.24 108.59,96.05 108.67,96.05 108.88,95.85 U34.5
  TOP w0.254: v1(106.92,97.09) 107.15,96.86 C130.1 ; C225.2 113.89,92.65 v1(115.22,92.65)
  TOP w0.381: v1(117.25,92.52) 117.25,94.3 115.29,96.27 C414.1
  BOTTOM w0.381: v1(106.92,97.09) 107.89,97.09 108.97,96.01 108.97,94.61 108.66,94.31 108.28,94.31 106.9,92.93 v1(106.08,92.93) 106.14,92.87 C131.1 106.14,91.24 106.75,90.63 113.2,90.63 v1(115.22,92.65) 117.13,92.65 v1(117.25,92.52)
RX+_PHY0: length 32.4
  TOP w0.114: R50.1 38.63,83.69 39.5,83.69 39.88,84.07 41.27,84.07 41.4,83.95 U27.6 U27.3 43.18,83.95 43.31,84.07 45.14,84.07 52.57,76.64 52.57,67.76 54.64,65.69 54.78,65.55 54.78,63.54 U10.B6
RX-_PHY0: length 32.5
  TOP w0.114: U10.A6 55.04,64.07 55.04,64.67 55.16,64.78 55.26,64.78 55.37,64.9 55.37,65.13 55.26,65.24 55.16,65.24 55.04,65.36 55.04,65.66 54.83,65.87 54.83,66.17 54.7,66.29 54.41,66.29 52.83,67.87 52.83,76.75 45.25,84.34 43.31,84.34 43.19,84.45 U27.4 U27.5 41.39,84.45 41.27,84.34 39.77,84.34 39.39,83.96 38.62,83.96 R18.1
SDIO0_CARD_DETECT: length 87
  TOP w0.127: v1(17.25,58.47) 16.76,58.95 16.76,60.84 17.98,62.05 24.59,62.05 27.15,64.62 45.09,64.62 49.15,60.56 49.15,59.51 50.19,58.47 50.19,58.19 50.47,57.91 51.6,57.91 U10.J2 ; v1(17.4,36.63) 18.16,35.86 R155.2 18.16,30.91 17.93,30.68 16.46,30.68 16.1,31.04 16.1,31.93 15.39,32.64 7.11,32.64 5.98,31.51 J13.9
  BOTTOM w0.127: v1(17.25,58.47) 18.21,57.51 18.21,37.44 v1(17.4,36.63)
SDIO0_CCLK_OUT: length 76.9
  TOP w0.127: R16.1 46.15,66.37 25.6,66.37 23.5,64.26 17.6,64.26 14.25,60.91 14.25,57.56 v1(13.92,57.23) ; J13.5 v1(3.3,26.27)
  BOTTOM w0.127: v1(3.3,26.27) 4.68,26.27 14.27,35.86 14.27,39.88 14.86,40.46 14.86,54.94 13.92,55.88 v1(13.92,57.23)
SDIO0_CCMD: length 97.1
  TOP w0.127: J13.3 12.17,24.06 13.27,25.17 R153.2 17.35,25.6 16.89,26.06 v1(14.58,26.06) ; v1(15.75,58.22) 15.75,61.28 17.41,62.94 23.7,62.94 26.14,65.38 45.41,65.38 49.91,60.88 49.91,59.87 50.29,59.49 51.53,59.49 U10.F2
  BOTTOM w0.127: v1(15.75,58.22) 15.75,57.12 17.17,55.7 17.17,38.25 15.95,37.03 15.95,34.75 14.58,33.38 v1(14.58,26.06)
SDIO0_CDATA0: length 98.9
  TOP w0.127: v1(13.21,58.85) 13.21,61.14 17.48,65.41 23.11,65.41 25.07,67.36 46.81,67.36 48.64,65.53 48.64,63.95 50.97,61.62 51.89,61.62 U10.E3 ; v1(16.26,39.17) 19.3,36.12 19.3,29.26 v1(19.02,28.98) R152.2 18.16,28.49 18,28.32 16.15,28.32 15.77,27.94 10.16,27.94 9.63,28.47 J13.7
  BOTTOM w0.127: v1(13.21,58.85) 13.74,58.85 15.02,57.57 15.02,56.86 16.38,55.5 16.38,39.29 v1(16.26,39.17)
SDIO0_CDATA1: length 98.7
  TOP w0.127: J13.8 10.49,29.57 11.66,28.4 15.6,28.4 16,28.8 16,29.08 16.41,29.49 18.02,29.49 18.16,29.63 R151.2 18.8,30.76 18.8,35.94 16.59,38.15 v1(16.26,38.15) ; U10.D3 52.38,61.94 51.01,61.94 48.9,64.05 48.9,65.68 46.96,67.61 24.56,67.61 22.73,65.79 17.48,65.79 12.67,60.99 v1(12.67,59.74)
  BOTTOM w0.127: v1(12.67,59.74) 13.41,59.74 15.42,57.73 15.42,56.97 16.81,55.58 16.81,38.71 v1(16.26,38.15)
SDIO0_CDATA2: length 97.2
  TOP w0.127: v1(17.2,57.3) 16.51,57.99 16.51,60.95 17.87,62.31 24.33,62.31 26.9,64.87 45.2,64.87 49.4,60.67 49.4,59.61 50.16,58.85 52.26,58.85 U10.H3 ; J13.1 12.06,21.87 13.69,23.49 16.26,23.49 v1(16.61,23.14) R154.2
  BOTTOM w0.127: v1(17.2,57.3) 17.53,56.97 17.53,38.05 16.37,36.89 16.37,34.4 14.94,32.97 14.94,26.47 15.85,25.55 15.85,23.9 v1(16.61,23.14)
SDIO0_CDATA3: length 97.8
  TOP w0.127: U10.G3 50.26,59.14 49.66,59.74 49.66,60.77 45.31,65.13 26.52,65.13 23.95,62.56 17.6,62.56 16.26,61.21 v1(16.26,57.3) ; R156.2 v1(16.6,24.16) 13.39,24.16 12.2,22.96 J13.2
  BOTTOM w0.127: v1(16.26,57.3) 16.89,57.94 17.32,57.94 17.88,57.38 17.88,37.8 16.88,36.79 16.88,34.28 15.24,32.64 15.24,26.77 16.6,25.41 v1(16.6,24.16)
SDIO0_CWPR: length 6.8
  TOP w0.127: R82.2 49.15,66.52 49.15,64.16 50.97,62.34 U10.C1
SDIO0_PWREN: length 84.8
  TOP w0.127: U10.J1 50.49,57.54 49.91,58.11 49.91,58.39 48.9,59.4 48.9,60.46 44.99,64.36 27.41,64.36 24.84,61.8 18.08,61.8 17.3,61.01 v1(17.3,59.82) ; R76.1 17.27,18.03 R149.1 16.59,20.65 v1(16.59,22.17)
  BOTTOM w0.127: v1(17.3,59.82) 17.3,59.36 18.54,58.12 18.54,35.31 15.6,32.36 15.6,27.08 17.18,25.49 17.18,22.77 v1(16.59,22.17)
SDIO_3318: length 84.7
  TOP w0.127: R152.1 v1(16.61,28.98) ; C62.1 R154.1 R156.1 R153.1 18.16,25.43 16.64,26.95 v1(16.61,26.95) ; U10.K5 U10.K4 53.19,57.12 50.54,57.12 49.66,58.01 49.66,58.28 48.64,59.3 48.64,59.44 C118.2 48.56,60.06 48.56,60.43 44.88,64.11 27.66,64.11 25.1,61.54 18.44,61.54 18.24,61.34 v1(18.24,59.82) ; R151.1 v1(16.61,30.12)
  BOTTOM w0.127: v1(16.61,26.95) 16.48,26.95 16.61,27.08 v1(16.61,28.98) v1(16.61,30.12) 15.88,30.86 15.88,32 18.85,34.98 18.85,58.5 18.24,59.11 v1(18.24,59.82)
SIM0_CARD_I/O: length 41.1
  TOP w0.127: J1.5 116.53,12.51 115.06,13.97 C489.1 115.47,15.14 115.7,15.37 115.7,17.02 116.08,17.4 126.62,17.4 130.43,21.21 130.43,29.21 129.49,30.15 v1(124.59,30.15)
  BOTTOM w0.127: R243.2 124.46,30.28 v1(124.59,30.15) 125.04,30.15 125.88,29.31 Q14.3
SIM0_CLK: length 70.3
  TOP w0.127: v1(128.41,25.71) 127.71,25.02 120.65,25.02 119.09,26.58 109.13,26.58 106.76,24.21 85.39,24.21 71.64,37.96 71.64,41.45 71.18,41.92 U10.AH26
  BOTTOM w0.127: v1(128.41,25.71) 128.4,25.72 R168.1
SIM0_CLK_OUT: length 33.1
  TOP w0.127: U24.8 v1(129.68,25.84)
  BOTTOM w0.127: J1.2 113.95,15.37 123.83,15.37 130.3,21.84 130.3,25.15 129.68,25.77 v1(129.68,25.84) 129.67,25.85 R269.1
SIM0_DATA: length 67.4
  TOP w0.127: v1(119.38,24.31) 113.13,24.31 111.72,22.9 85.13,22.9 70.74,37.29 70.74,42.77 U10.AG25
  BOTTOM w0.127: R38.1 122.58,21.87 120.14,24.31 v1(119.38,24.31)
SIM0_DET: length 69.2
  TOP w0.127: U10.AH25 70.38,37.28 85.13,22.53 111.86,22.53 113.04,23.71 119.42,23.71 119.89,23.24 119.89,22.1 v1(119.38,21.59) ; R39.1 v1(120.14,16.81)
  BOTTOM w0.127: v1(120.14,16.81) 119.76,17.2 119.76,21.21 v1(119.38,21.59)
SIM0_PWREN: length 86.5
  TOP w0.127: v1(124.6,29) 124.08,29.51 121.21,29.51 119.76,28.07 114.38,28.07 113.54,27.23 108.08,27.23 106.25,25.4 86.06,25.4 72.69,38.76 72.69,41.27 72.48,41.49 72.1,41.49 71.58,42.01 71.58,42.74 U10.AG26 ; v1(124.6,29) 126.71,29 127.14,28.57 U24.10 ; v1(124.6,29) U24.12 ; U24.1 v1(122.06,23.54) 122.52,24 125.91,24 v1(126.12,23.79) 125.87,23.54 U24.4
  BOTTOM w0.127: R271.2 126.24,21.87 126.49,22.12 126.49,23.42 v1(126.12,23.79) ; v1(122.06,23.54) 122.06,24.14 123.95,26.03 123.95,28.35 v1(124.6,29)
SIM0_PWREN_CTL: length 8
  TOP w0.127: R242.1 123.85,20.22 124.6,20.96 U24.3
SIM0_RST: length 76.2
  TOP w0.127: U10.AF24 69.98,43.54 69.98,37.3 85.05,22.23 111.98,22.23 113,23.24 118.87,23.24 v1(119.38,22.73) ; U24.5 v1(127.14,23.92)
  BOTTOM w0.127: v1(119.38,22.73) 121.41,20.7 126.36,20.7 127.14,21.47 v1(127.14,23.92)
SIM0_RST_OUT: length 28.8
  TOP w0.127: v1(128.41,23.92) U24.6 128.41,20.69 126.14,18.41 115.7,18.41 114.3,17.02 114.3,15.62 113.82,15.14 C491.1 111.89,13.08 111.53,12.72 J1.3
  BOTTOM w0.127: R268.1 128.63,23.7 v1(128.41,23.92)
SPDIF_OUT_BOOT_SEL1: length 50.9
  TOP w0.127: v1(67.82,77.22) 67.82,67.56 67.61,67.36 67.61,63.5 U10.B22 ; U9.1 85.34,102.33 85.34,99.95 86.36,98.93 R91.1 86.72,97.05 87,96.77 87,95.12 85.22,93.34 82.39,93.34 v1(80.39,91.35)
  BOTTOM w0.127: v1(80.39,91.35) 74.26,85.22 73.25,85.22 67.82,79.78 v1(67.82,77.22)
